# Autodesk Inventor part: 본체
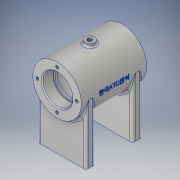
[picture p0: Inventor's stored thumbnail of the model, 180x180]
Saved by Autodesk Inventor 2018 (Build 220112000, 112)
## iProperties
Created: 2020-07
Part Number: 본체
Material: 알루미늄 6061
Document SubType Name: Modeling
Designer: home
Density: 2.7 g/cm^3
Appearance: 알루미늄 - 평지
Mass: 305.248 g
Surface Area: 357.573 cm^2
Volume: 113.055 cm^3
Author: home
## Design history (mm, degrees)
sketch "스케치1"
  geometry: L1 (26, 35)-(17, 35); L2 (16, 34)-(16, 23.3); L3 (15.7, 23)-(14, 23); L4 (14, 23)-(14, 21); L5 (14, 21)-(18, 21); L6 (21, 18)-(21, -18); L7 (18, -21)-(14, -21); L8 (14, -21)-(14, -23); L9 (14, -23)-(15.7, -23); L10 (16, -23.3)-(16, -34); L11 (17, -35)-(26, -35); L12 (26, -35)-(26, 35); L13 (0, 46.883)-(0, -78.319); L14 (17, 35)-(16, 34); L15 (17, -35)-(16, -34); A1 r 3 centre (18, 18) between (21, 18) and (18, 21); A2 r 3 centre (18, -18) between (18, -21) and (21, -18); A3 r 0.3 centre (15.7, 23.3) between (15.7, 23) and (16, 23.3); A4 r 0.3 centre (15.7, -23.3) between (16, -23.3) and (15.7, -23); 7 further points
  constraints: 30 end point, 17 point on line, 9 perpendicular, 8 point on circle, 8 tangent, 4 centre point, 2 equal radius, 1 horizontal, 1 vertical
  dimensions: "d0" = 70 distance of L11.end L1.start; "d1" = 52 diameter of L12 L13; "d2" = 32 diameter of L2 L13; "d3" = 28 diameter of L4 L13; "d4" = 42 diameter of L6 L13; "d5" = 12 distance of point (16, 35) point (16, 23); "d6" = 2 distance of L3.end L4.end; "d7" = 42 distance of point (21, 21) point (21, -21); "d8" = 12 distance of point (16, -23) point (16, -35); "d9" = 35 distance from line of point (0, 0) L1; "d10" = 1 distance of L1.end point (16, 35); "d11" = 1 distance of L2.start point (16, 35) (= d10); "d12" = 1 distance of L11.start point (16, -35) (= d10); "d13" = 1 distance of L10.end point (16, -35) (= d12); "d14" = 3 radius of A1; "d15" = 0.3 radius of A3; "d80" = 11.88336 distance from line of L13.start L1; "d81" = 113.3187 distance from line of L13.end L1
revolve "회전1" sketch "스케치1" stored, may be unused: angle "d16" = 90 deg
node "작업 평면1"
sketch "스케치2"
  geometry: L1 (26, 30)-(-26, 30); L2 (-26, 30)-(-26, 20); L3 (-26, 20)-(26, 20); L4 (26, 20)-(26, 30); L5 (26, -20)-(-26, -20); L6 (-26, -20)-(-26, -30); L7 (-26, -30)-(26, -30); L8 (26, -30)-(26, -20); L9 (26, 30)-(-26, -30); 2 further points
  constraints: 18 end point, 4 parallel, 2 horizontal, 2 perpendicular, 2 point on line, 1 coincident, 1 midpoint
  dimensions: "d18" = 52 distance of L3.end L2.end; "d19" = 10 distance of L2.end L1.end; "d20" = 10 distance of L6.end L5.end; "d21" = 60 distance between parallel lines of L1 L7
extrude "돌출1" join sketch "스케치2" stored distance "d22" = 0; taper "d23" = 0 deg
sketch "스케치3"
  geometry: L1 (-26, 30)-(26, 30) reference; 2 further points
  dimensions: "d24" = 5 distance from line of L1 point (20, 25); "d25" = 20 horizontal distance of point (0, 0) point (20, 25)
hole "구멍1" sketch "스케치3" at (20, 25) diameter "d26" = 4.134; stored, may be unused: countersink angle "d30" = 90 deg, drill point angle "d32" = 118 deg; dims "d27" = 8, "d28" = 4, "d29" = 2, "d31" = 10
sketch "스케치4"
  geometry: 2 further points
  constraints: 1 vertical alignment
  dimensions: "d39" = 21 distance of point (0, 0) point (0, 21)
hole "구멍2" sketch "스케치4" at (0, 21) diameter "d40" = 3.242; stored, may be unused: countersink angle "d44" = 90 deg, drill point angle "d46" = 118 deg; dims "d41" = 8, "d42" = 4, "d43" = 2, "d45" = 10
node "작업 평면2"
sketch "스케치5"
  geometry: C1 r 5 at (0, 0); 1 further point
  constraints: 1 centre point, 1 coincident
  dimensions: "d51" = 10 diameter of C1
extrude "돌출2" join sketch "스케치5" stored distance "d52" = 10; taper "d53" = 0 deg
sketch "스케치6"
  geometry: C1 r 5 at (0, 0) reference; 1 further point
hole "구멍3" sketch "스케치6" at (0, 0) diameter "d54" = 5.188; stored, may be unused: countersink angle "d58" = 90 deg, drill point angle "d60" = 118 deg; dims "d55" = 12, "d56" = 4, "d57" = 2, "d59" = 16
node "작업 평면3"
fillet "모깎기1" dims "d64" = 3, "d79" = 2
sketch "스케치8"
  geometry: L1 (0, 0)-(-9.919, -27.251); L2 (26, -64)-(26, 0) reference
  constraints: 2 end point
  dimensions: "d66" = 29 distance of L1.start L1.end; "d70" = 20 deg angle of L2 L1
node "작업 평면4"
sketch "스케치9"
  geometry: C1 r 6 at (0, 0); 1 further point
  constraints: 1 centre point, 1 coincident
  dimensions: "d67" = 12 diameter of C1
extrude "돌출3" join sketch "스케치9" stored distance "d68" = 0; taper "d69" = 0 deg
sketch "스케치7"
  geometry: 2 further points
  constraints: 1 coincident, 1 other
feature "엠보싱1" sketch "스케치7" dims "d62" = 0.5, "d63" = 0
fillet "모깎기2" dims "d71" = 2
sketch "스케치10"
  geometry: C1 r 6 at (0, 0) reference; 1 further point
hole "구멍4" sketch "스케치10" at (0, 0) diameter "d72" = 5.188; stored, may be unused: countersink angle "d76" = 90 deg, drill point angle "d78" = 118 deg; dims "d73" = 12, "d74" = 4, "d75" = 2, "d77" = 16
node "솔리드1"
pattern_linear "직사각형 패턴1" dims "d35" = 40, "d38" = 50
pattern_circular "원형 패턴1" dims angle "d48" = 360 deg
mirror "미러1"
other parameters: "d17" = -64, "d50" = 29, "d61" = 26
